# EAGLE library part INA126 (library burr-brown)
Instrumentation Amplifier Micropower, Single and Dual Versions
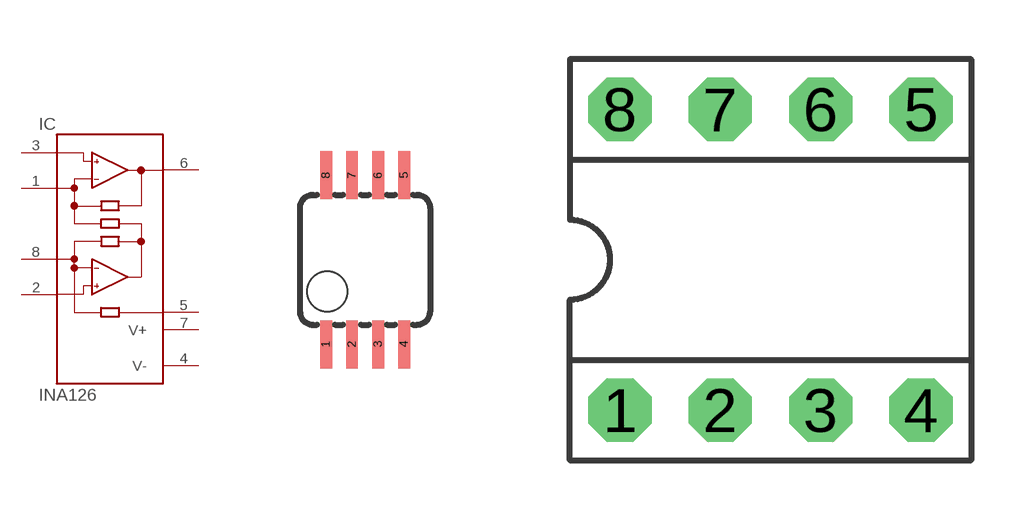
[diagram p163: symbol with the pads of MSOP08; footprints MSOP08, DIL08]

Designator prefix IC

## INA126E (MF: TEXAS INSTRUMENTS; MPN: INA126E/250; OC_FARNELL: 1575427; OC_NEWARK: 74C9777)  [MSOP08]
1  RG  pas
2  -IN  in
3  +IN  in
4  V-  pwr
5  REF  pas
6  OUT  out
7  V+  pwr
8  RG  pas

## INA126P (MF: TEXAS INSTRUMENT CONNECTORS; MPN: INA126P; OC_FARNELL: 1509595; OC_NEWARK: 74C9780)  [DIL08]
Pads as for MSOP08

## INA126U (MF: TEXAS INSTRUMENTS; MPN: INA126U; OC_FARNELL: 1212409; OC_NEWARK: 84K8003)  [SO08]
Pads as for MSOP08

## Footprint MSOP08 (pad centres in mm)
Mini Small Outline Package
smd 0.3 x 1.2: 1 -0.976,-2.113; 2 -0.326,-2.113; 3 0.324,-2.113; 4 0.974,-2.113; 5 0.974,2.112; 6 0.324,2.112; 7 -0.326,2.112; 8 -0.976,2.112

## Footprint DIL08 (pad centres in mm)
Dual In Line
drill 0.813 pad 1.6 octagon: 1 -3.81,-3.81; 2 -1.27,-3.81; 3 1.27,-3.81; 4 3.81,-3.81; 5 3.81,3.81; 6 1.27,3.81; 7 -1.27,3.81; 8 -3.81,3.81

## Footprint SO08 (pad centres in mm)
Small Outline Package
smd 0.61 x 2.21: 1 -1.905,-2.616; 2 -0.635,-2.616; 3 0.635,-2.616; 4 1.905,-2.616; 5 1.905,2.616; 6 0.635,2.616; 7 -0.635,2.616; 8 -1.905,2.616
